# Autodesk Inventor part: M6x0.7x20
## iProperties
Created: 2009-02
Part Number: M6x0.7x20
Material: 강, 연강
Description: 6각머리 태핑 나사
Document SubType Name: Modeling
Standard: KS B 1003
Designer: KYOUNG IL JANG
Standards Organization: KS
Language: ko-KR
Size Designation: M 6 x 20
Categories: <MemberInstance><Categories><Category DisplayName="조임쇠" InternalName="e4da775c-781d-43d5-af7c-5136215cf5a6" Mnemonic="FSTN"><Category DisplayName="볼트" InternalN
Density: 7.86 g/cm^3
Mass: 7.48273 g
Surface Area: 7.64101 cm^2
Volume: 0.952001 cm^3
Vendor: CBT Solutions
Company: 한국ATC센터
IsCustomPart: 1
Author: KYOUNG IL JANG
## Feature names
1. Fillet2
